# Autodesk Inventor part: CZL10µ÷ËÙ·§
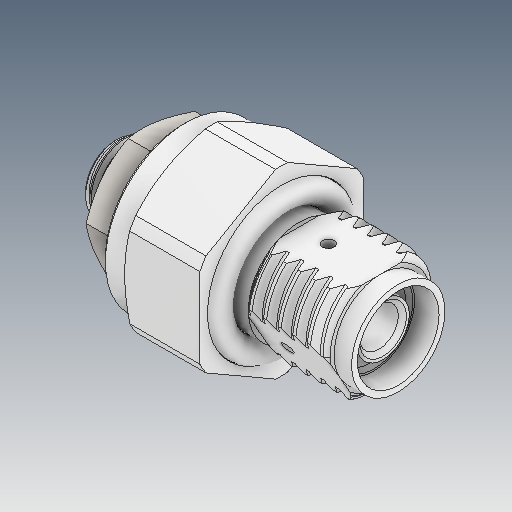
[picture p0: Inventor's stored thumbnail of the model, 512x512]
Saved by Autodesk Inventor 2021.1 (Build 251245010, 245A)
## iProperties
Created: 2021-05
Part Number: CZL10µ÷ËÙ·§
Material: Ogólny
Document SubType Name: Modeling
Designer: user
Density: 1 g/cm^3
Appearance: Domyślna
Author: user
Revision Number: ÈÎºÎ
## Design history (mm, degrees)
feature "ÊäÈë2"
feature "ÊäÈë3"
feature "ÊäÈë5"
node "Bryła1"
node "Bryła2"
node "Bryła3"
